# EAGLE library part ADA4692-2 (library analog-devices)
Low Power, 3.6 MHz, Low Noise, Rail-to-Rail Output, Operational Amplifiers Source: http://www.analog.com/static/imported-files/data_sheets/ADA4691-2_4692-2_4692-4.pdf
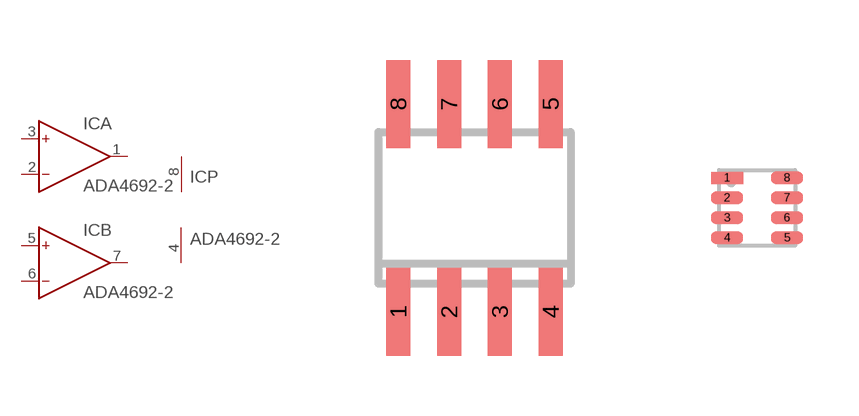
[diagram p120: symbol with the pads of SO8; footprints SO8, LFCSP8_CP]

Designator prefix IC; gates A=OP B=OP P=PWR+-

## ADA4692-2R (MPN: ADA4692-2ARZ; OC_FARNELL: 1760810; OC_NEWARK: 05R6523)  [SO8]
1  A:OUT  out
2  A:IN-  in
3  A:IN+  in
4  P:V-  pwr
5  B:IN+  in
6  B:IN-  in
7  B:OUT  out
8  P:V+  pwr

## ADA4692-2CP (OC_FARNELL: 1827383; OC_NEWARK: unknown)  [LFCSP8_CP]
Pads as for SO8

## Footprint SO8 (pad centres in mm)
8-Lead Small Outline IC (SO-8) Source: http://www.analog.com/UploadedFiles/Data_Sheets/703465986AD8611_2_0.pdf
smd 0.6 x 2.2: 1 -1.905,-2.6; 2 -0.635,-2.6; 3 0.635,-2.6; 4 1.905,-2.6; 5 1.905,2.6; 6 0.635,2.6; 7 -0.635,2.6; 8 -1.905,2.6

## Footprint LFCSP8_CP (pad centres in mm)
8-Lead Lead Frame Chip Scale Package LFCSP_WD 2 mm × 2 mm Body, Very Very Thin, Dual Lead Source: http://www.analog.com/static/imported-files/data_sheets/ADA4075-2.pdf
smd 0.8 x 0.3: 1 -0.75,0.75; 2 -0.75,0.25; 3 -0.75,-0.25; 4 -0.75,-0.75; 5 0.75,-0.75; 6 0.75,-0.25; 7 0.75,0.25; 8 0.75,0.75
